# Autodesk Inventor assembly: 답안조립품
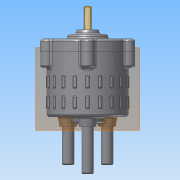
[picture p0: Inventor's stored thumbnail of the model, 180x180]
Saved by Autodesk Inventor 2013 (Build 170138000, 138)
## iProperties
Created: 2016-01
Part Number: 답안조립품
Document SubType Name: Assembly
Designer: Administrator
Author: Administrator
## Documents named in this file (14)
- C:\Users\Administrator\Desktop\360106V1028\답안조립품.iam
- C:\Users\Administrator\Desktop\360106V1028\본체.ipt
- C:\Users\Administrator\Desktop\360106V1028\커버.ipt
- C:\Users\Administrator\Desktop\360106V1028\베어링 NA 4900.ipt
- C:\Users\Administrator\Desktop\360106V1028\오일실.ipt
- C:\Users\Administrator\Desktop\360106V1028\메인 축.ipt
- C:\Users\Administrator\Desktop\360106V1028\멈춤링 22 x 1.2.ipt
- C:\Users\Administrator\Desktop\360106V1028\판캠.ipt
- C:\Users\Administrator\Desktop\360106V1028\멈춤링 10 x 1.ipt
- C:\Users\Administrator\Desktop\360106V1028\M5x0.8x20.ipt
- C:\Users\Administrator\Desktop\360106V1028\슬라이드 축.ipt
- C:\Users\Administrator\Desktop\360106V1028\가변 스프링 - 1.ipt
- C:\Users\Administrator\Desktop\360106V1028\가변 스프링 - 2.ipt
- C:\Users\Administrator\Desktop\360106V1028\가변 스프링 - 3.ipt
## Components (8 placed, 4 different names)
1. M5x0.8x20:1
2. M5x0.8x20:2
3. M5x0.8x20:3
4. M5x0.8x20:4
5. M5x0.8x20:5
6. 가변 스프링 - 1:1
7. 가변 스프링 - 2:1
8. 가변 스프링 - 3:1
